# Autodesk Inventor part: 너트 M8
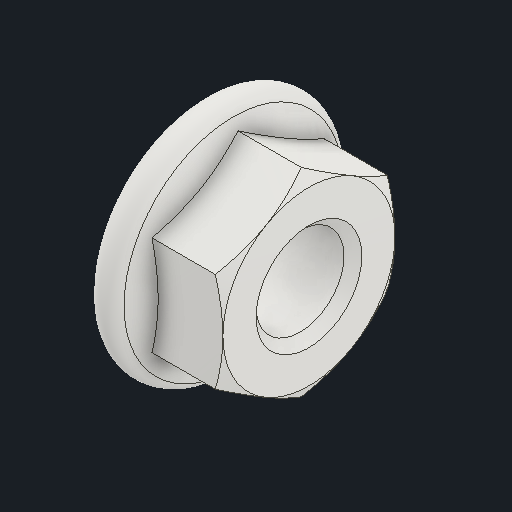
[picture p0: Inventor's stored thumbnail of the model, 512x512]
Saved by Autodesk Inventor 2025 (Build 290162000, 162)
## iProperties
Created: 2025-08
Part Number: 너트 M8
Material: 스테인리스강
Description: 플랜지붙이 6각 너트 - 일반 스레드
Document SubType Name: Modeling
Designer: infra012
Density: 8 g/cm^3
Appearance: 기본값
Author: jhkim
Sending System: Autodesk Inventor 2026
Preprocessor: ST-DEVELOPER v20.1
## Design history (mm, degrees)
sketch "스케치1"
  geometry: 1 further point
  constraints: 1 other
feature "Solid1"
node "솔리드1"
